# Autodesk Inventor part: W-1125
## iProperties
Author: Administrator
Revision Number: A
Created: 2001-03
Part Number: W-1125
Document SubType Name: Modeling
Designer: Administrator
Description: HUB, 1.125" DIA
Control State: 0
Master: False
Checked Out: False
PropertySet Name: Design Tracking Control
Shininess: 20.0
PropertySet Name: _Private Model Information
Density: 0.0
Volumn: 0.0
Area: 0.0
PropertySet Name: Model Information
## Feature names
1. Derived Body1 [Tagging]
